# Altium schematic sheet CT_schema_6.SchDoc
size 306 x 171 mm
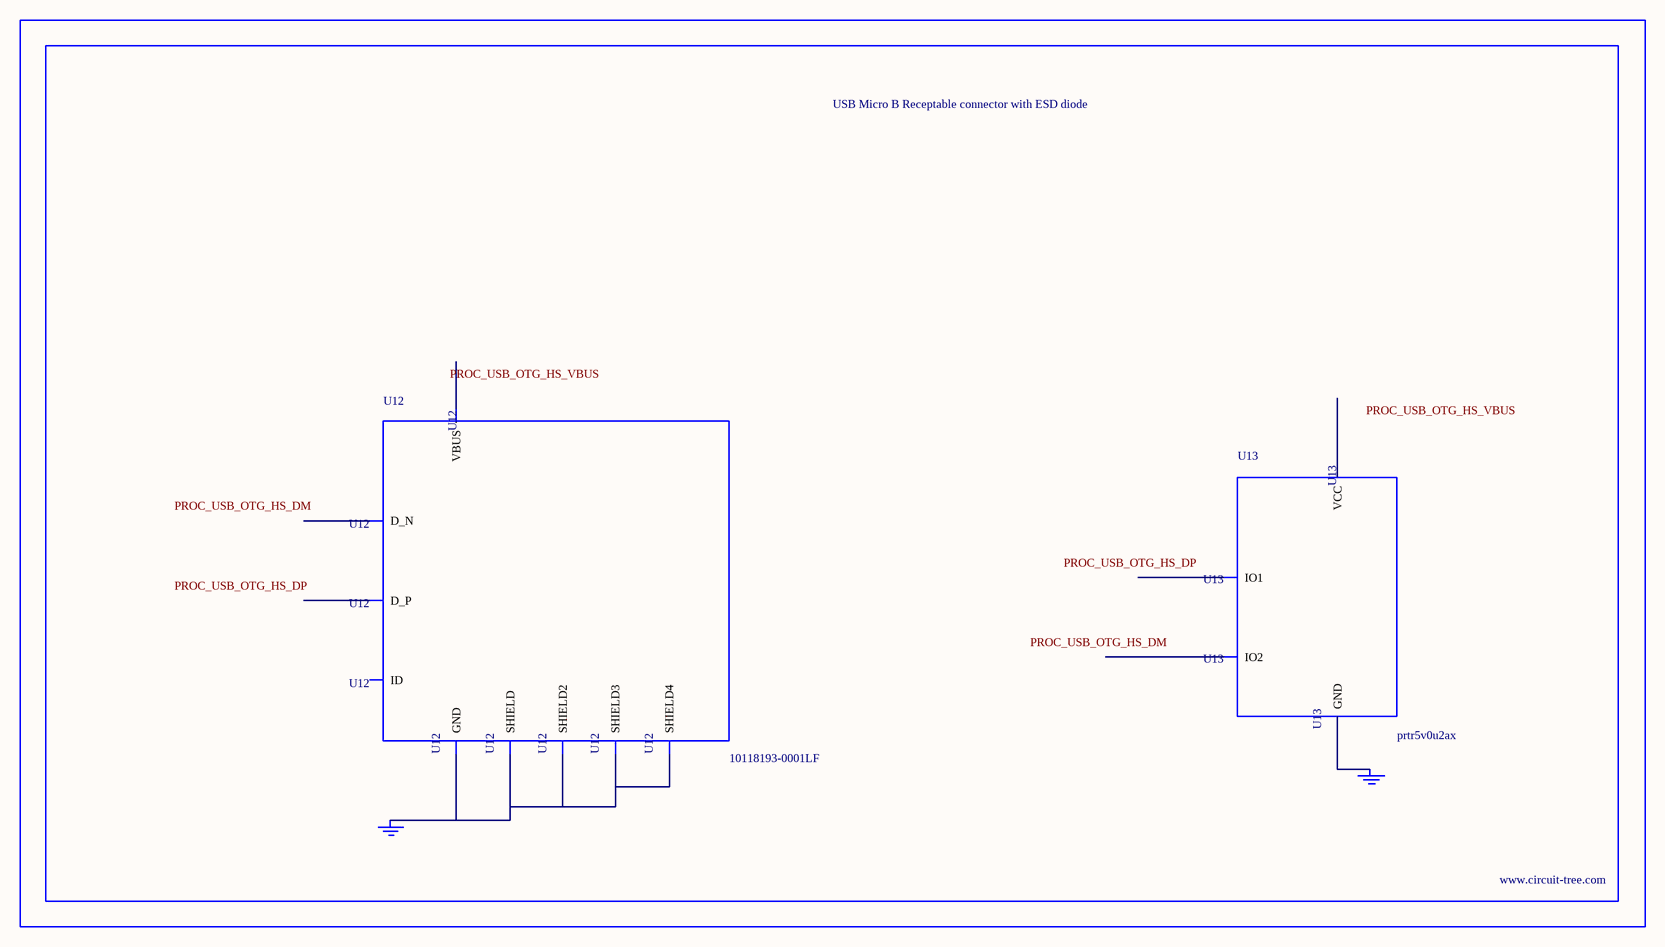
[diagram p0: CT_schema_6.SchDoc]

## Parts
BORDER5  (no value)
GND_INSTANCE_5_0  (no value)
GND_INSTANCE_5_1  (no value)
U12  10118193-0001LF  [FCI_10118193-0001LF]
U13  prtr5v0u2ax  [SOT143B]

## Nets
NetGND_INSTANCE_5_0_0: GND_INSTANCE_5_0.0(GND) U12.5(GND) U12.6(SHIELD) U12.7(SHIELD2) U12.8(SHIELD3) U12.9(SHIELD4)
NetGND_INSTANCE_5_1_0: GND_INSTANCE_5_1.0(GND) U13.1(GND)

Not connected (* = marked no-connect by the designer): U12 1(VBUS) 2(D_N) 3(D_P) 4(ID); U13 2(IO1) 3(IO2) 4(VCC)

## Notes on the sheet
- Labels drawn without touching a wire or pin: PROC_USB_OTG_HS_DM, PROC_USB_OTG_HS_DP, PROC_USB_OTG_HS_VBUS

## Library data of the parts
BORDER5 = BORDER_PAGE5
GND_INSTANCE_5_0 GND_INSTANCE_5_1 = GND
